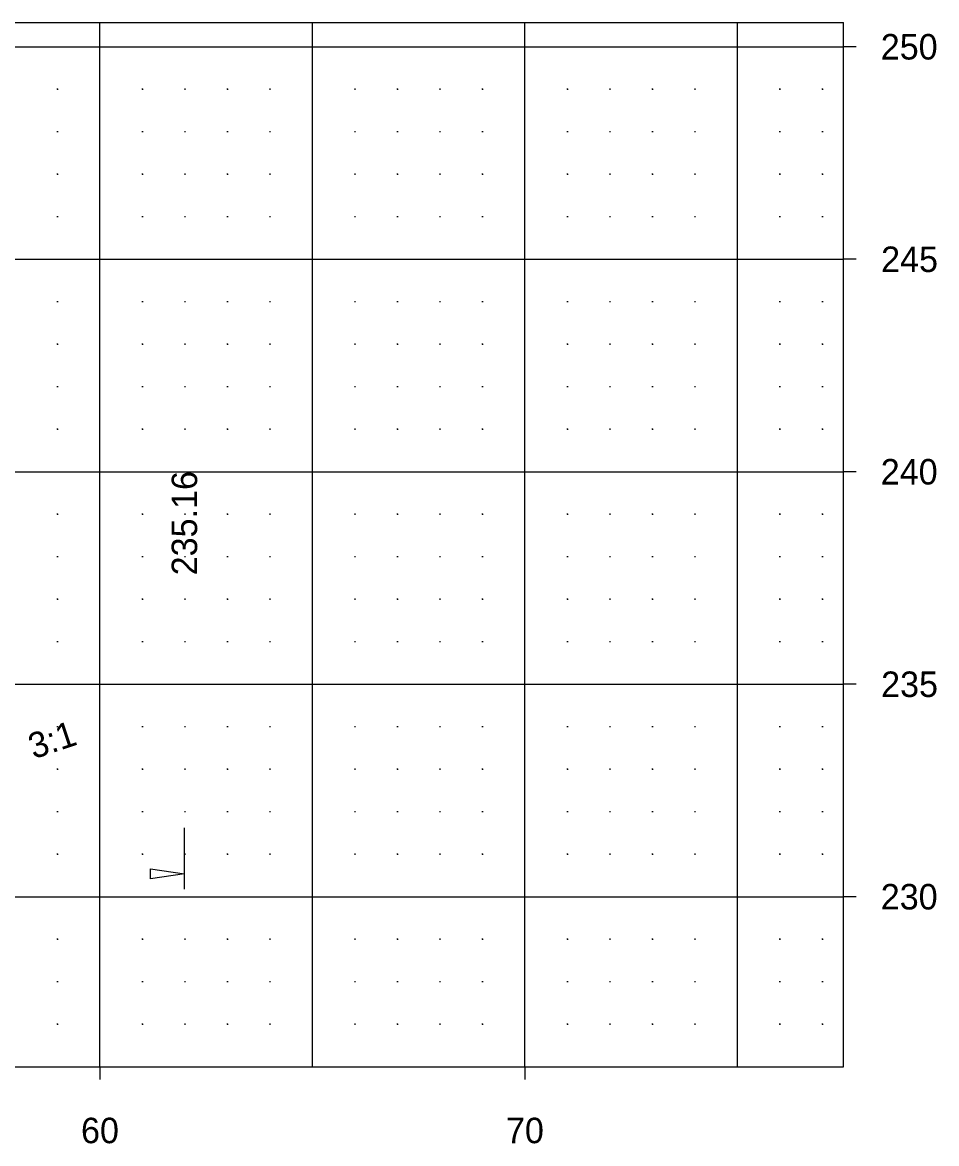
# Model space of a CAD drawing. Extents: x -80 to 80, y 222 to 253.
# Drawn here: x 58.18 to 79.69, y 224.19 to 250.57 of the extents above; entities that cross this region are included whole.
import ezdxf

# ---------------------------------------------------------------- set-up
doc = ezdxf.new("R2010")
doc.units = 0
for name, color, linetype in [('DSN_DRFT_XS Border Grid', 7, 'Continuous'), ('DSN_DRFT_XS Grid Annotations', 7, 'Continuous'), ('DSN_DRFT_XS Grid Major', 7, 'Continuous'), ('DSN_DRFT_XS Grid Minor', 7, 'Continuous'), ('DSN_DRFT_XS MOT STG Annotations', 7, 'Continuous'), ('DSN_RDWY_XS Annotation', 7, 'Continuous')]:
    doc.layers.add(name, color=color, linetype=linetype)

msp = doc.modelspace()

# ---------------------------------------------------------------- linework, layer by layer
at = {"layer": 'DSN_DRFT_XS Border Grid'}
for p, q in [((-77.5, 250.573), (77.5, 250.573)), ((77.5, 226), (77.5, 250.573)), ((-77.5, 226), (77.5, 226))]:
    msp.add_line(p, q, dxfattribs=at)
at = {"layer": 'DSN_DRFT_XS Grid Major'}
for p, q in [((60, 226), (60, 250.573)), ((65, 226), (65, 250.573)), ((70, 226), (70, 250.573)), ((75, 226), (75, 250.573)), ((-77.5, 250), (77.5, 250)), ((77.8, 250), (77.5, 250)), ((-77.5, 245), (77.5, 245)), ((77.8, 245), (77.5, 245)), ((-77.5, 240), (77.5, 240)), ((77.8, 240), (77.5, 240)), ((-77.5, 235), (77.5, 235)), ((77.8, 235), (77.5, 235)), ((-77.5, 230), (77.5, 230)), ((77.8, 230), (77.5, 230)), ((60, 226), (60, 225.7)), ((70, 226), (70, 225.7))]:
    msp.add_line(p, q, dxfattribs=at)
at = {"layer": 'DSN_DRFT_XS Grid Minor'}
for p, q in [((59.012, 249), (58.988, 249)), ((59, 249.012), (59, 248.988)), ((61.012, 249), (60.988, 249)), ((61, 249.012), (61, 248.988)), ((62.012, 249), (61.988, 249)), ((62, 249.012), (62, 248.988)), ((63.012, 249), (62.988, 249)), ((63, 249.012), (63, 248.988)), ((64.012, 249), (63.988, 249)), ((64, 249.012), (64, 248.988)), ((66.012, 249), (65.988, 249)), ((66, 249.012), (66, 248.988)), ((67.012, 249), (66.988, 249)), ((67, 249.012), (67, 248.988)), ((68.012, 249), (67.988, 249)), ((68, 249.012), (68, 248.988)), ((69.012, 249), (68.988, 249)), ((69, 249.012), (69, 248.988)), ((71.012, 249), (70.988, 249)), ((71, 249.012), (71, 248.988)), ((72.012, 249), (71.988, 249)), ((72, 249.012), (72, 248.988)), ((73.012, 249), (72.988, 249)), ((73, 249.012), (73, 248.988)), ((74.012, 249), (73.988, 249)), ((74, 249.012), (74, 248.988)), ((76.012, 249), (75.988, 249)), ((76, 249.012), (76, 248.988)), ((77.012, 249), (76.988, 249)), ((77, 249.012), (77, 248.988)), ((59.012, 248), (58.988, 248)), ((59, 248.012), (59, 247.988)), ((61.012, 248), (60.988, 248)), ((61, 248.012), (61, 247.988)), ((62.012, 248), (61.988, 248)), ((62, 248.012), (62, 247.988)), ((63.012, 248), (62.988, 248)), ((63, 248.012), (63, 247.988)), ((64.012, 248), (63.988, 248)), ((64, 248.012), (64, 247.988)), ((66.012, 248), (65.988, 248)), ((66, 248.012), (66, 247.988)), ((67.012, 248), (66.988, 248)), ((67, 248.012), (67, 247.988)), ((68.012, 248), (67.988, 248)), ((68, 248.012), (68, 247.988)), ((69.012, 248), (68.988, 248)), ((69, 248.012), (69, 247.988)), ((71.012, 248), (70.988, 248)), ((71, 248.012), (71, 247.988)), ((72.012, 248), (71.988, 248)), ((72, 248.012), (72, 247.988)), ((73.012, 248), (72.988, 248)), ((73, 248.012), (73, 247.988)), ((74.012, 248), (73.988, 248)), ((74, 248.012), (74, 247.988)), ((76.012, 248), (75.988, 248)), ((76, 248.012), (76, 247.988)), ((77.012, 248), (76.988, 248)), ((77, 248.012), (77, 247.988)), ((59.012, 247), (58.988, 247)), ((59, 247.012), (59, 246.988)), ((61.012, 247), (60.988, 247)), ((61, 247.012), (61, 246.988)), ((62.012, 247), (61.988, 247)), ((62, 247.012), (62, 246.988)), ((63.012, 247), (62.988, 247)), ((63, 247.012), (63, 246.988)), ((64.012, 247), (63.988, 247)), ((64, 247.012), (64, 246.988)), ((66.012, 247), (65.988, 247)), ((66, 247.012), (66, 246.988)), ((67.012, 247), (66.988, 247)), ((67, 247.012), (67, 246.988)), ((68.012, 247), (67.988, 247)), ((68, 247.012), (68, 246.988)), ((69.012, 247), (68.988, 247)), ((69, 247.012), (69, 246.988)), ((71.012, 247), (70.988, 247)), ((71, 247.012), (71, 246.988)), ((72.012, 247), (71.988, 247)), ((72, 247.012), (72, 246.988)), ((73.012, 247), (72.988, 247)), ((73, 247.012), (73, 246.988)), ((74.012, 247), (73.988, 247)), ((74, 247.012), (74, 246.988)), ((76.012, 247), (75.988, 247)), ((76, 247.012), (76, 246.988)), ((77.012, 247), (76.988, 247)), ((77, 247.012), (77, 246.988)), ((59.012, 246), (58.988, 246)), ((59, 246.012), (59, 245.988)), ((61.012, 246), (60.988, 246)), ((61, 246.012), (61, 245.988)), ((62.012, 246), (61.988, 246)), ((62, 246.012), (62, 245.988)), ((63.012, 246), (62.988, 246)), ((63, 246.012), (63, 245.988)), ((64.012, 246), (63.988, 246)), ((64, 246.012), (64, 245.988)), ((66.012, 246), (65.988, 246)), ((66, 246.012), (66, 245.988)), ((67.012, 246), (66.988, 246)), ((67, 246.012), (67, 245.988)), ((68.012, 246), (67.988, 246)), ((68, 246.012), (68, 245.988)), ((69.012, 246), (68.988, 246)), ((69, 246.012), (69, 245.988)), ((71.012, 246), (70.988, 246)), ((71, 246.012), (71, 245.988)), ((72.012, 246), (71.988, 246)), ((72, 246.012), (72, 245.988)), ((73.012, 246), (72.988, 246)), ((73, 246.012), (73, 245.988)), ((74.012, 246), (73.988, 246)), ((74, 246.012), (74, 245.988)), ((76.012, 246), (75.988, 246)), ((76, 246.012), (76, 245.988)), ((77.012, 246), (76.988, 246)), ((77, 246.012), (77, 245.988)), ((59.012, 244), (58.988, 244)), ((59, 244.012), (59, 243.988)), ((61.012, 244), (60.988, 244)), ((61, 244.012), (61, 243.988)), ((62.012, 244), (61.988, 244)), ((62, 244.012), (62, 243.988)), ((63.012, 244), (62.988, 244)), ((63, 244.012), (63, 243.988)), ((64.012, 244), (63.988, 244)), ((64, 244.012), (64, 243.988)), ((66.012, 244), (65.988, 244)), ((66, 244.012), (66, 243.988)), ((67.012, 244), (66.988, 244)), ((67, 244.012), (67, 243.988)), ((68.012, 244), (67.988, 244)), ((68, 244.012), (68, 243.988)), ((69.012, 244), (68.988, 244)), ((69, 244.012), (69, 243.988)), ((71.012, 244), (70.988, 244)), ((71, 244.012), (71, 243.988)), ((72.012, 244), (71.988, 244)), ((72, 244.012), (72, 243.988)), ((73.012, 244), (72.988, 244)), ((73, 244.012), (73, 243.988)), ((74.012, 244), (73.988, 244)), ((74, 244.012), (74, 243.988)), ((76.012, 244), (75.988, 244)), ((76, 244.012), (76, 243.988)), ((77.012, 244), (76.988, 244)), ((77, 244.012), (77, 243.988)), ((59.012, 243), (58.988, 243)), ((59, 243.012), (59, 242.988)), ((61.012, 243), (60.988, 243)), ((61, 243.012), (61, 242.988)), ((62.012, 243), (61.988, 243)), ((62, 243.012), (62, 242.988)), ((63.012, 243), (62.988, 243)), ((63, 243.012), (63, 242.988)), ((64.012, 243), (63.988, 243)), ((64, 243.012), (64, 242.988)), ((66.012, 243), (65.988, 243)), ((66, 243.012), (66, 242.988)), ((67.012, 243), (66.988, 243)), ((67, 243.012), (67, 242.988)), ((68.012, 243), (67.988, 243)), ((68, 243.012), (68, 242.988)), ((69.012, 243), (68.988, 243)), ((69, 243.012), (69, 242.988)), ((71.012, 243), (70.988, 243)), ((71, 243.012), (71, 242.988)), ((72.012, 243), (71.988, 243)), ((72, 243.012), (72, 242.988)), ((73.012, 243), (72.988, 243)), ((73, 243.012), (73, 242.988)), ((74.012, 243), (73.988, 243)), ((74, 243.012), (74, 242.988)), ((76.012, 243), (75.988, 243)), ((76, 243.012), (76, 242.988)), ((77.012, 243), (76.988, 243)), ((77, 243.012), (77, 242.988)), ((59.012, 242), (58.988, 242)), ((59, 242.012), (59, 241.988)), ((61.012, 242), (60.988, 242)), ((61, 242.012), (61, 241.988)), ((62.012, 242), (61.988, 242)), ((62, 242.012), (62, 241.988)), ((63.012, 242), (62.988, 242)), ((63, 242.012), (63, 241.988)), ((64.012, 242), (63.988, 242)), ((64, 242.012), (64, 241.988)), ((66.012, 242), (65.988, 242)), ((66, 242.012), (66, 241.988)), ((67.012, 242), (66.988, 242)), ((67, 242.012), (67, 241.988)), ((68.012, 242), (67.988, 242)), ((68, 242.012), (68, 241.988)), ((69.012, 242), (68.988, 242)), ((69, 242.012), (69, 241.988)), ((71.012, 242), (70.988, 242)), ((71, 242.012), (71, 241.988)), ((72.012, 242), (71.988, 242)), ((72, 242.012), (72, 241.988)), ((73.012, 242), (72.988, 242)), ((73, 242.012), (73, 241.988)), ((74.012, 242), (73.988, 242)), ((74, 242.012), (74, 241.988)), ((76.012, 242), (75.988, 242)), ((76, 242.012), (76, 241.988)), ((77.012, 242), (76.988, 242)), ((77, 242.012), (77, 241.988)), ((59.012, 241), (58.988, 241)), ((59, 241.012), (59, 240.988)), ((61.012, 241), (60.988, 241)), ((61, 241.012), (61, 240.988)), ((62.012, 241), (61.988, 241)), ((62, 241.012), (62, 240.988)), ((63.012, 241), (62.988, 241)), ((63, 241.012), (63, 240.988)), ((64.012, 241), (63.988, 241)), ((64, 241.012), (64, 240.988)), ((66.012, 241), (65.988, 241)), ((66, 241.012), (66, 240.988)), ((67.012, 241), (66.988, 241)), ((67, 241.012), (67, 240.988)), ((68.012, 241), (67.988, 241)), ((68, 241.012), (68, 240.988)), ((69.012, 241), (68.988, 241)), ((69, 241.012), (69, 240.988)), ((71.012, 241), (70.988, 241)), ((71, 241.012), (71, 240.988)), ((72.012, 241), (71.988, 241)), ((72, 241.012), (72, 240.988)), ((73.012, 241), (72.988, 241)), ((73, 241.012), (73, 240.988)), ((74.012, 241), (73.988, 241)), ((74, 241.012), (74, 240.988)), ((76.012, 241), (75.988, 241)), ((76, 241.012), (76, 240.988)), ((77.012, 241), (76.988, 241)), ((77, 241.012), (77, 240.988)), ((59.012, 239), (58.988, 239)), ((59, 239.012), (59, 238.988)), ((61.012, 239), (60.988, 239)), ((61, 239.012), (61, 238.988)), ((62.012, 239), (61.988, 239)), ((62, 239.012), (62, 238.988)), ((63.012, 239), (62.988, 239)), ((63, 239.012), (63, 238.988)), ((64.012, 239), (63.988, 239)), ((64, 239.012), (64, 238.988)), ((66.012, 239), (65.988, 239)), ((66, 239.012), (66, 238.988)), ((67.012, 239), (66.988, 239)), ((67, 239.012), (67, 238.988)), ((68.012, 239), (67.988, 239)), ((68, 239.012), (68, 238.988)), ((69.012, 239), (68.988, 239)), ((69, 239.012), (69, 238.988)), ((71.012, 239), (70.988, 239)), ((71, 239.012), (71, 238.988)), ((72.012, 239), (71.988, 239)), ((72, 239.012), (72, 238.988)), ((73.012, 239), (72.988, 239)), ((73, 239.012), (73, 238.988)), ((74.012, 239), (73.988, 239)), ((74, 239.012), (74, 238.988)), ((76.012, 239), (75.988, 239)), ((76, 239.012), (76, 238.988)), ((77.012, 239), (76.988, 239)), ((77, 239.012), (77, 238.988)), ((59.012, 238), (58.988, 238)), ((59, 238.012), (59, 237.988)), ((61.012, 238), (60.988, 238)), ((61, 238.012), (61, 237.988)), ((62.012, 238), (61.988, 238)), ((62, 238.012), (62, 237.988)), ((63.012, 238), (62.988, 238)), ((63, 238.012), (63, 237.988)), ((64.012, 238), (63.988, 238)), ((64, 238.012), (64, 237.988)), ((66.012, 238), (65.988, 238)), ((66, 238.012), (66, 237.988)), ((67.012, 238), (66.988, 238)), ((67, 238.012), (67, 237.988)), ((68.012, 238), (67.988, 238)), ((68, 238.012), (68, 237.988)), ((69.012, 238), (68.988, 238)), ((69, 238.012), (69, 237.988)), ((71.012, 238), (70.988, 238)), ((71, 238.012), (71, 237.988)), ((72.012, 238), (71.988, 238)), ((72, 238.012), (72, 237.988)), ((73.012, 238), (72.988, 238)), ((73, 238.012), (73, 237.988)), ((74.012, 238), (73.988, 238)), ((74, 238.012), (74, 237.988)), ((76.012, 238), (75.988, 238)), ((76, 238.012), (76, 237.988)), ((77.012, 238), (76.988, 238)), ((77, 238.012), (77, 237.988)), ((59.012, 237), (58.988, 237)), ((59, 237.012), (59, 236.988)), ((61.012, 237), (60.988, 237)), ((61, 237.012), (61, 236.988)), ((62.012, 237), (61.988, 237)), ((62, 237.012), (62, 236.988)), ((63.012, 237), (62.988, 237)), ((63, 237.012), (63, 236.988)), ((64.012, 237), (63.988, 237)), ((64, 237.012), (64, 236.988)), ((66.012, 237), (65.988, 237)), ((66, 237.012), (66, 236.988)), ((67.012, 237), (66.988, 237)), ((67, 237.012), (67, 236.988)), ((68.012, 237), (67.988, 237)), ((68, 237.012), (68, 236.988)), ((69.012, 237), (68.988, 237)), ((69, 237.012), (69, 236.988)), ((71.012, 237), (70.988, 237)), ((71, 237.012), (71, 236.988)), ((72.012, 237), (71.988, 237)), ((72, 237.012), (72, 236.988)), ((73.012, 237), (72.988, 237)), ((73, 237.012), (73, 236.988)), ((74.012, 237), (73.988, 237)), ((74, 237.012), (74, 236.988)), ((76.012, 237), (75.988, 237)), ((76, 237.012), (76, 236.988)), ((77.012, 237), (76.988, 237)), ((77, 237.012), (77, 236.988)), ((59.012, 236), (58.988, 236)), ((59, 236.012), (59, 235.988)), ((61.012, 236), (60.988, 236)), ((61, 236.012), (61, 235.988)), ((62.012, 236), (61.988, 236)), ((62, 236.012), (62, 235.988)), ((63.012, 236), (62.988, 236)), ((63, 236.012), (63, 235.988)), ((64.012, 236), (63.988, 236)), ((64, 236.012), (64, 235.988)), ((66.012, 236), (65.988, 236)), ((66, 236.012), (66, 235.988)), ((67.012, 236), (66.988, 236)), ((67, 236.012), (67, 235.988)), ((68.012, 236), (67.988, 236)), ((68, 236.012), (68, 235.988)), ((69.012, 236), (68.988, 236)), ((69, 236.012), (69, 235.988)), ((71.012, 236), (70.988, 236)), ((71, 236.012), (71, 235.988)), ((72.012, 236), (71.988, 236)), ((72, 236.012), (72, 235.988)), ((73.012, 236), (72.988, 236)), ((73, 236.012), (73, 235.988)), ((74.012, 236), (73.988, 236)), ((74, 236.012), (74, 235.988)), ((76.012, 236), (75.988, 236)), ((76, 236.012), (76, 235.988)), ((77.012, 236), (76.988, 236)), ((77, 236.012), (77, 235.988)), ((59, 234.012), (59, 233.988)), ((61, 234.012), (61, 233.988)), ((62, 234.012), (62, 233.988)), ((63, 234.012), (63, 233.988)), ((64, 234.012), (64, 233.988)), ((66, 234.012), (66, 233.988)), ((67, 234.012), (67, 233.988)), ((68, 234.012), (68, 233.988)), ((69, 234.012), (69, 233.988)), ((71, 234.012), (71, 233.988)), ((72, 234.012), (72, 233.988)), ((73, 234.012), (73, 233.988)), ((74, 234.012), (74, 233.988)), ((76, 234.012), (76, 233.988)), ((77, 234.012), (77, 233.988)), ((59.012, 234), (58.988, 234)), ((61.012, 234), (60.988, 234)), ((62.012, 234), (61.988, 234)), ((63.012, 234), (62.988, 234)), ((64.012, 234), (63.988, 234)), ((66.012, 234), (65.988, 234)), ((67.012, 234), (66.988, 234)), ((68.012, 234), (67.988, 234)), ((69.012, 234), (68.988, 234)), ((71.012, 234), (70.988, 234)), ((72.012, 234), (71.988, 234)), ((73.012, 234), (72.988, 234)), ((74.012, 234), (73.988, 234)), ((76.012, 234), (75.988, 234)), ((77.012, 234), (76.988, 234)), ((59.012, 233), (58.988, 233)), ((59, 233.012), (59, 232.988)), ((61.012, 233), (60.988, 233)), ((61, 233.012), (61, 232.988)), ((62.012, 233), (61.988, 233)), ((62, 233.012), (62, 232.988)), ((63.012, 233), (62.988, 233)), ((63, 233.012), (63, 232.988)), ((64.012, 233), (63.988, 233)), ((64, 233.012), (64, 232.988)), ((66.012, 233), (65.988, 233)), ((66, 233.012), (66, 232.988)), ((67.012, 233), (66.988, 233)), ((67, 233.012), (67, 232.988)), ((68.012, 233), (67.988, 233)), ((68, 233.012), (68, 232.988)), ((69.012, 233), (68.988, 233)), ((69, 233.012), (69, 232.988)), ((71.012, 233), (70.988, 233)), ((71, 233.012), (71, 232.988)), ((72.012, 233), (71.988, 233)), ((72, 233.012), (72, 232.988)), ((73.012, 233), (72.988, 233)), ((73, 233.012), (73, 232.988)), ((74.012, 233), (73.988, 233)), ((74, 233.012), (74, 232.988)), ((76.012, 233), (75.988, 233)), ((76, 233.012), (76, 232.988)), ((77.012, 233), (76.988, 233)), ((77, 233.012), (77, 232.988)), ((59.012, 232), (58.988, 232)), ((59, 232.012), (59, 231.988)), ((61.012, 232), (60.988, 232)), ((61, 232.012), (61, 231.988)), ((62.012, 232), (61.988, 232)), ((62, 232.012), (62, 231.988)), ((63.012, 232), (62.988, 232)), ((63, 232.012), (63, 231.988)), ((64.012, 232), (63.988, 232)), ((64, 232.012), (64, 231.988)), ((66.012, 232), (65.988, 232)), ((66, 232.012), (66, 231.988)), ((67.012, 232), (66.988, 232)), ((67, 232.012), (67, 231.988)), ((68.012, 232), (67.988, 232)), ((68, 232.012), (68, 231.988)), ((69.012, 232), (68.988, 232)), ((69, 232.012), (69, 231.988)), ((71.012, 232), (70.988, 232)), ((71, 232.012), (71, 231.988)), ((72.012, 232), (71.988, 232)), ((72, 232.012), (72, 231.988)), ((73.012, 232), (72.988, 232)), ((73, 232.012), (73, 231.988)), ((74.012, 232), (73.988, 232)), ((74, 232.012), (74, 231.988)), ((76.012, 232), (75.988, 232)), ((76, 232.012), (76, 231.988)), ((77.012, 232), (76.988, 232)), ((77, 232.012), (77, 231.988)), ((59.012, 231), (58.988, 231)), ((59, 231.012), (59, 230.988)), ((61.012, 231), (60.988, 231)), ((61, 231.012), (61, 230.988)), ((62.012, 231), (61.988, 231)), ((62, 231.012), (62, 230.988)), ((63.012, 231), (62.988, 231)), ((63, 231.012), (63, 230.988)), ((64.012, 231), (63.988, 231)), ((64, 231.012), (64, 230.988)), ((66.012, 231), (65.988, 231)), ((66, 231.012), (66, 230.988)), ((67.012, 231), (66.988, 231)), ((67, 231.012), (67, 230.988)), ((68.012, 231), (67.988, 231)), ((68, 231.012), (68, 230.988)), ((69.012, 231), (68.988, 231)), ((69, 231.012), (69, 230.988)), ((71.012, 231), (70.988, 231)), ((71, 231.012), (71, 230.988)), ((72.012, 231), (71.988, 231)), ((72, 231.012), (72, 230.988)), ((73.012, 231), (72.988, 231)), ((73, 231.012), (73, 230.988)), ((74.012, 231), (73.988, 231)), ((74, 231.012), (74, 230.988)), ((76.012, 231), (75.988, 231)), ((76, 231.012), (76, 230.988)), ((77.012, 231), (76.988, 231)), ((77, 231.012), (77, 230.988)), ((59.012, 229), (58.988, 229)), ((59, 229.012), (59, 228.988)), ((61.012, 229), (60.988, 229)), ((61, 229.012), (61, 228.988)), ((62.012, 229), (61.988, 229)), ((62, 229.012), (62, 228.988)), ((63.012, 229), (62.988, 229)), ((63, 229.012), (63, 228.988)), ((64.012, 229), (63.988, 229)), ((64, 229.012), (64, 228.988)), ((66.012, 229), (65.988, 229)), ((66, 229.012), (66, 228.988)), ((67.012, 229), (66.988, 229)), ((67, 229.012), (67, 228.988)), ((68.012, 229), (67.988, 229)), ((68, 229.012), (68, 228.988)), ((69.012, 229), (68.988, 229)), ((69, 229.012), (69, 228.988)), ((71.012, 229), (70.988, 229)), ((71, 229.012), (71, 228.988)), ((72.012, 229), (71.988, 229)), ((72, 229.012), (72, 228.988)), ((73.012, 229), (72.988, 229)), ((73, 229.012), (73, 228.988)), ((74.012, 229), (73.988, 229)), ((74, 229.012), (74, 228.988)), ((76.012, 229), (75.988, 229)), ((76, 229.012), (76, 228.988)), ((77.012, 229), (76.988, 229)), ((77, 229.012), (77, 228.988)), ((59.012, 228), (58.988, 228)), ((59, 228.012), (59, 227.988)), ((61.012, 228), (60.988, 228)), ((61, 228.012), (61, 227.988)), ((62.012, 228), (61.988, 228)), ((62, 228.012), (62, 227.988)), ((63.012, 228), (62.988, 228)), ((63, 228.012), (63, 227.988)), ((64.012, 228), (63.988, 228)), ((64, 228.012), (64, 227.988)), ((66.012, 228), (65.988, 228)), ((66, 228.012), (66, 227.988)), ((67.012, 228), (66.988, 228)), ((67, 228.012), (67, 227.988)), ((68.012, 228), (67.988, 228)), ((68, 228.012), (68, 227.988)), ((69.012, 228), (68.988, 228)), ((69, 228.012), (69, 227.988)), ((71.012, 228), (70.988, 228)), ((71, 228.012), (71, 227.988)), ((72.012, 228), (71.988, 228)), ((72, 228.012), (72, 227.988)), ((73.012, 228), (72.988, 228)), ((73, 228.012), (73, 227.988)), ((74.012, 228), (73.988, 228)), ((74, 228.012), (74, 227.988)), ((76.012, 228), (75.988, 228)), ((76, 228.012), (76, 227.988)), ((77.012, 228), (76.988, 228)), ((77, 228.012), (77, 227.988)), ((59.012, 227), (58.988, 227)), ((59, 227.012), (59, 226.988)), ((61.012, 227), (60.988, 227)), ((61, 227.012), (61, 226.988)), ((62.012, 227), (61.988, 227)), ((62, 227.012), (62, 226.988)), ((63.012, 227), (62.988, 227)), ((63, 227.012), (63, 226.988)), ((64.012, 227), (63.988, 227)), ((64, 227.012), (64, 226.988)), ((66.012, 227), (65.988, 227)), ((66, 227.012), (66, 226.988)), ((67.012, 227), (66.988, 227)), ((67, 227.012), (67, 226.988)), ((68.012, 227), (67.988, 227)), ((68, 227.012), (68, 226.988)), ((69.012, 227), (68.988, 227)), ((69, 227.012), (69, 226.988)), ((71.012, 227), (70.988, 227)), ((71, 227.012), (71, 226.988)), ((72.012, 227), (71.988, 227)), ((72, 227.012), (72, 226.988)), ((73.012, 227), (72.988, 227)), ((73, 227.012), (73, 226.988)), ((74.012, 227), (73.988, 227)), ((74, 227.012), (74, 226.988)), ((76.012, 227), (75.988, 227)), ((76, 227.012), (76, 226.988)), ((77.012, 227), (76.988, 227)), ((77, 227.012), (77, 226.988))]:
    msp.add_line(p, q, dxfattribs=at)
at = {"layer": 'DSN_DRFT_XS MOT STG Annotations'}
msp.add_line((61.988, 230.178), (61.988, 231.618), dxfattribs=at)
msp.add_lwpolyline([(61.188, 230.658), (61.988, 230.538), (61.188, 230.418)], close=True, dxfattribs=at)

# ---------------------------------------------------------------- texts
at = {"layer": 'DSN_DRFT_XS Grid Annotations'}
for s, p in [('250', (78.375, 249.7)), ('245', (78.383, 244.7)), ('240', (78.375, 239.7)), ('235', (78.383, 234.7)), ('230', (78.375, 229.7)), ('60', (59.555, 224.2)), ('70', (69.555, 224.2))]:
    msp.add_text(s, height=0.6, dxfattribs=at).set_placement(p)
at = {"layer": 'DSN_RDWY_XS Annotation'}
for s, rotation, p in [('235.16', 90, (62.288, 237.563)), ('3:1', 18.4349, (58.44, 233.233))]:
    msp.add_text(s, height=0.6, rotation=rotation, dxfattribs=at).set_placement(p)

doc.saveas('drawing.dxf')
